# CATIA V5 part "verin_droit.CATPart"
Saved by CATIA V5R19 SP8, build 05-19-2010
Part number: verin_droit
Bounding box of the stored display mesh (mm): x 575 to 775, y -59.975 to 59.975, z 75 to 1200
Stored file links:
  G:\EU_thinkMotion\CFAO_2010\MMS_groupe2\MMS_groupe2\OK\mmartini\mmartiniCFAO\verin_droit.CATPart
  C:\Users\Mathieu Martini\Desktop\CFAO\Animation\CFAO.CATProduct
  G:\EU_thinkMotion\CFAO_2010\MMS_groupe2\MMS_groupe2\OK\mmartini\mmartiniCFAO\Squelette.CATPart
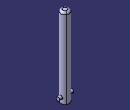
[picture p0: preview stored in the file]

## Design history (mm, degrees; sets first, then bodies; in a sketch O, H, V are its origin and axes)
External parameters (linked from other documents)
  External.diametre_canon = 150 mm
  External.diametre_verin = 120 mm
AxisSystem1: origin (0, 0, 0), X (1, 0, 0), Y (0, 1, 0), Z (0, 0, 1)
Set1
  Sketch1 on Plane1, origin (675, 0, 0), H (0, 1, 0), V (0, 0, 1)
    line L1 (0, 75) -> (60, 75)
    line L2 (60, 75) -> (60, 1200)
    line L3 (60, 1200) -> (0, 1200)
    line L4 (0, 1200) -> (0, 75)
    point P5 (0, 150)
    reference projected point E1 (0, 150) from Point1
    distance P5 L1 = 75 {= External.diametre_canon /2}
    distance P5 L3 = 1050 {= External.diametre_canon *7}
    length L3 = 60 {= External.diametre_verin /2}
    horizontal: L1 H, L3 H
    vertical: L2 V, L4 V
    coincidence: P5 L4, E1 P5
Set2
  Plane1 "Plan_verin_droit": linked copy from another document
  Point1 "pt_canonvertical": linked copy from another document
  Point2 "Point_verin_droit": linked copy from another document
  Plane2 "Plan_rayon_ext_verin_droit": linked copy from another document
Body1 (main body)
  Shaft1: profile Sketch1, axis Sketch1.L4, angle 360
  Fillet1: radius 30 {= External.diametre_verin /4}, on edge [face of Shaft1 from Sketch1.L3 | face of Shaft1 from Sketch1.L2]
  Sketch2 on Plane1, origin (675, 0, 0), H (0, 1, 0), V (0, 0, 1)
    circle A1 centre (0, 150) radius 24
    point P1 (0, 150)
    reference projected point E1 (0, 150) from Point1
    radius A1 = 24 {= External.diametre_verin  /5}
    coincidence: P1 E1
  Pad1: profile Sketch2, direction (1, 0, 0), length 100 {= External.diametre_canon /1.5}, opposite side length 100 {= External.diametre_canon /1.5}
  Sketch3 on face of Shaft1 from Sketch1.L1, origin (0, 0, 75), H (1, 0, 0), V (0, -1, 0)
    circle A1 centre (675, 0) radius 48
    point P1 (675, 0)
    reference projected point E1 (675, 0) from Point2
    radius A1 = 48 {= (External.diametre_verin -External.diametre_verin /5)/2}
    coincidence: P1 E1
  Pocket1: profile Sketch3, direction (0, 0, 1), length 1012.5 {= External.diametre_canon *6.75}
